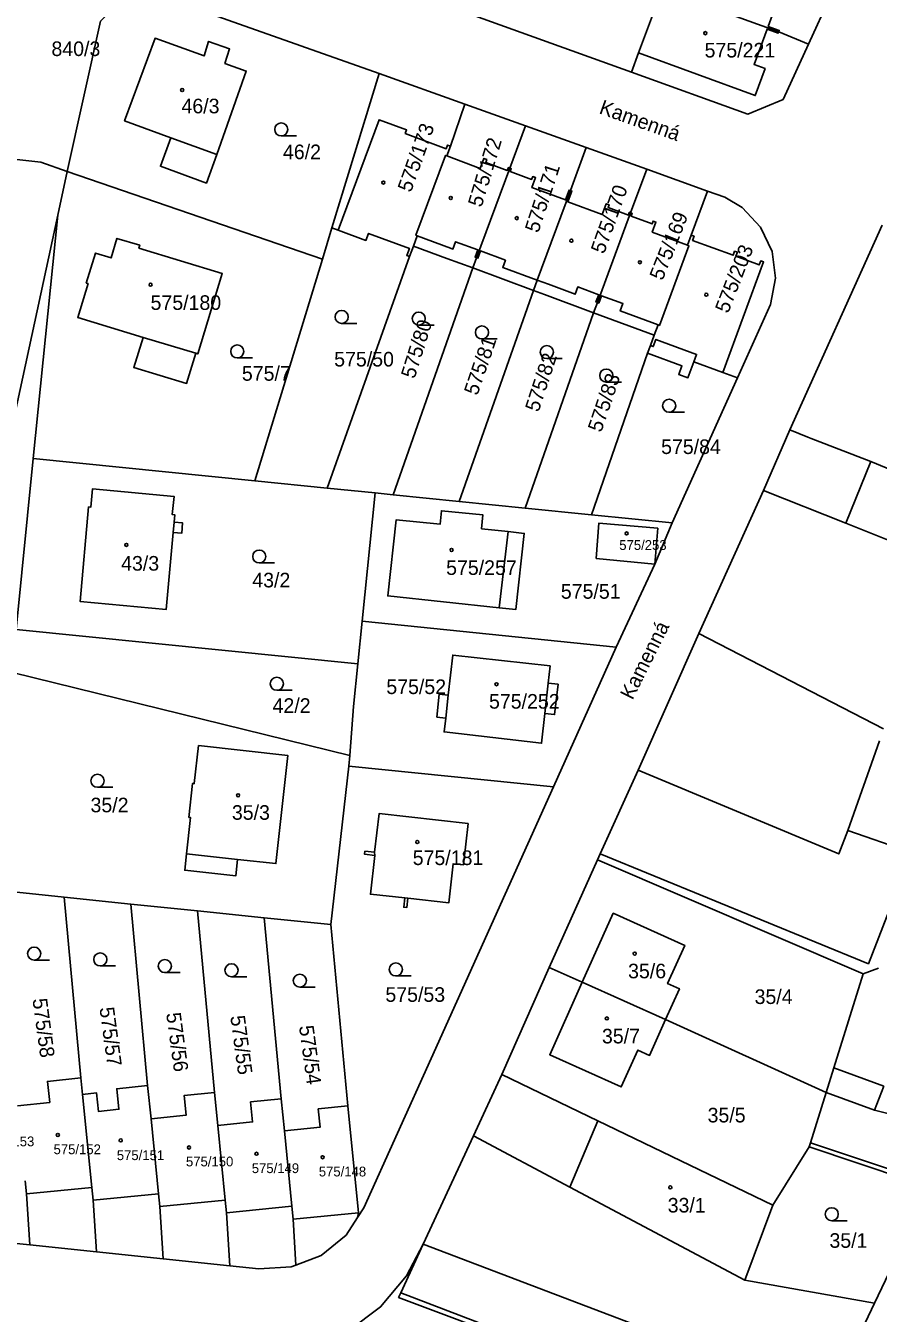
# Model space of a CAD drawing. Extents: x -737240 to -735272, y -1119606 to -1117878.
# Drawn here: x -737081.3 to -736982.1, y -1119014.9 to -1118864.9 of the extents above; entities that cross this region are included whole.
import ezdxf

# ---------------------------------------------------------------- set-up
doc = ezdxf.new("R2010")
doc.units = 0
for name, color, linetype in [('Level 1', 7, 'Continuous'), ('Level 15', 7, 'Continuous'), ('Level 16', 7, 'Continuous'), ('Level 18', 7, 'Continuous'), ('Level 19', 7, 'Continuous'), ('Level 25', 7, 'Continuous'), ('Level 4', 7, 'Continuous')]:
    doc.layers.add(name, color=color, linetype=linetype)

msp = doc.modelspace()

# ---------------------------------------------------------------- linework, layer by layer
at = {"layer": 'Level 1'}
for p, q in [((-737007.25, -1118860.74), (-737009.97, -1118868.1)), ((-736993.66, -1118865.64), (-737007.25, -1118860.74)), ((-736990.21, -1118867.1), (-736987.06, -1118860.23)), ((-737076.46, -1118881.9), (-737072.59, -1118864.42)), ((-737030.53, -1118863.26), (-737010.8, -1118870.36)), ((-736990.21, -1118867.1), (-736993.66, -1118865.64)), ((-737009.97, -1118868.1), (-737010.8, -1118870.36)), ((-737040.17, -1118870.49), (-737045.66, -1118888.46)), ((-737030.19, -1118874.06), (-737040.17, -1118870.49)), ((-737031.87, -1118878.96), (-737030.19, -1118874.06)), ((-737023.12, -1118876.59), (-737030.19, -1118874.06)), ((-737024.97, -1118881.51), (-737023.12, -1118876.59)), ((-737016.06, -1118879.12), (-737023.12, -1118876.59)), ((-737032.29, -1118880.11), (-737031.87, -1118878.96)), ((-737017.9, -1118884.13), (-737016.06, -1118879.12)), ((-737009, -1118881.66), (-737016.06, -1118879.12)), ((-737077.57, -1118886.99), (-737076.46, -1118881.9)), ((-737046.77, -1118892.11), (-737076.46, -1118881.9)), ((-737028.84, -1118891.96), (-737024.97, -1118881.51)), ((-737010.9, -1118886.72), (-737009, -1118881.66)), ((-737001.94, -1118884.19), (-737009, -1118881.66)), ((-737021.77, -1118894.57), (-737017.9, -1118884.13)), ((-737001.94, -1118884.19), (-737003.84, -1118889.33)), ((-737077.57, -1118886.99), (-737092.86, -1118957.66)), ((-737080.43, -1118915.33), (-737077.57, -1118886.99)), ((-737014.77, -1118897.17), (-737010.9, -1118886.72)), ((-737045.66, -1118888.46), (-737046.77, -1118892.11)), ((-737045.66, -1118888.46), (-737044.94, -1118888.73)), ((-736992.35, -1118912.01), (-736981.62, -1118888.15)), ((-737036.18, -1118890.6), (-737035.73, -1118889.4)), ((-737003.84, -1118889.33), (-737004.27, -1118890.5)), ((-737036.62, -1118891.81), (-737036.18, -1118890.6)), ((-737046.77, -1118892.11), (-737054.65, -1118917.93)), ((-737036.62, -1118891.81), (-737046.23, -1118918.78)), ((-737038.54, -1118919.56), (-737029.28, -1118893.15)), ((-737029.28, -1118893.15), (-737028.84, -1118891.96)), ((-737029.28, -1118893.15), (-737022.21, -1118895.77)), ((-737022.21, -1118895.77), (-737021.77, -1118894.57)), ((-737030.85, -1118920.33), (-737022.21, -1118895.77)), ((-737015.21, -1118898.36), (-737014.77, -1118897.17)), ((-737015.21, -1118898.36), (-737023.16, -1118921.11)), ((-737015.21, -1118898.36), (-737008.15, -1118900.97)), ((-737007.7, -1118899.78), (-737008.15, -1118900.97)), ((-737008.59, -1118902.18), (-737008.92, -1118903.06)), ((-737008.15, -1118900.97), (-737008.59, -1118902.18)), ((-737008.92, -1118903.06), (-737015.45, -1118921.89)), ((-737003.53, -1118904.06), (-737000.18, -1118905.3)), ((-737006.06, -1118922.84), (-736998.45, -1118905.94)), ((-737000.18, -1118905.3), (-736998.45, -1118905.94)), ((-736995.45, -1118919.05), (-736992.35, -1118912.01)), ((-737082.43, -1118935.23), (-737080.43, -1118915.33)), ((-737080.43, -1118915.33), (-737054.65, -1118917.93)), ((-737054.65, -1118917.93), (-737046.23, -1118918.78)), ((-737046.23, -1118918.78), (-737040.63, -1118919.35)), ((-737040.63, -1118919.35), (-737042.16, -1118934.27)), ((-737040.63, -1118919.35), (-737038.54, -1118919.56)), ((-737030.85, -1118920.33), (-737038.54, -1118919.56)), ((-737002.97, -1118935.72), (-736995.45, -1118919.05)), ((-737023.16, -1118921.11), (-737030.85, -1118920.33)), ((-737015.45, -1118921.89), (-737023.16, -1118921.11)), ((-737015.45, -1118921.89), (-737006.06, -1118922.84)), ((-737008.07, -1118927.62), (-737006.06, -1118922.84)), ((-737012.57, -1118937.31), (-737008.07, -1118927.62)), ((-737042.16, -1118934.27), (-737042.64, -1118939.25)), ((-737012.57, -1118937.31), (-737042.16, -1118934.27)), ((-737082.43, -1118935.23), (-737042.64, -1118939.25)), ((-737010.03, -1118951.63), (-737002.97, -1118935.72)), ((-736981.48, -1118946.83), (-737002.97, -1118935.72)), ((-737019.89, -1118953.57), (-737012.57, -1118937.31)), ((-737043.57, -1118949.91), (-737082.82, -1118940.25)), ((-737043.57, -1118949.91), (-737043.71, -1118951.15)), ((-737043.71, -1118951.15), (-737045.79, -1118969.61)), ((-737019.89, -1118953.57), (-737043.71, -1118951.15)), ((-737014.45, -1118961.37), (-737010.03, -1118951.63)), ((-737020.36, -1118974.59), (-737014.76, -1118962.06)), ((-737014.76, -1118962.06), (-737014.45, -1118961.37)), ((-737014.76, -1118962.06), (-736983.85, -1118975.35)), ((-737076.82, -1118966.41), (-737084.58, -1118965.6)), ((-737074.89, -1118987.46), (-737076.82, -1118966.41)), ((-737069.07, -1118967.21), (-737076.82, -1118966.41)), ((-737067.11, -1118988.35), (-737069.07, -1118967.21)), ((-737061.3, -1118968.01), (-737069.07, -1118967.21)), ((-737053.55, -1118968.81), (-737061.3, -1118968.01)), ((-737059.34, -1118989.15), (-737061.3, -1118968.01)), ((-737045.79, -1118969.61), (-737053.55, -1118968.81)), ((-737051.57, -1118989.89), (-737053.55, -1118968.81)), ((-737043.8, -1118990.72), (-737045.79, -1118969.61)), ((-737025.89, -1118987.06), (-737020.36, -1118974.59)), ((-737016.53, -1118976.3), (-737020.36, -1118974.59)), ((-736983.85, -1118975.35), (-736987.26, -1118986.29)), ((-736983.85, -1118975.35), (-736982.04, -1118974.66)), ((-737006.82, -1118980.64), (-737016.53, -1118976.3)), ((-736988.15, -1118989.15), (-737006.82, -1118980.64)), ((-737074.69, -1118989.38), (-737074.89, -1118987.46)), ((-737029.19, -1118994.2), (-737025.89, -1118987.06)), ((-737025.89, -1118987.06), (-737014.71, -1118992.46)), ((-736987.26, -1118986.29), (-736988.15, -1118989.15)), ((-737066.71, -1118992.22), (-737067.11, -1118988.35)), ((-737073.61, -1119000.2), (-737074.69, -1118989.38)), ((-737058.94, -1118992.98), (-737059.34, -1118989.15)), ((-737051.19, -1118993.62), (-737051.57, -1118989.89)), ((-736988.15, -1118989.15), (-736989.98, -1118995.02)), ((-737042.56, -1119003.16), (-737043.8, -1118990.72)), ((-737065.85, -1119000.94), (-737066.71, -1118992.22)), ((-737058.08, -1119001.68), (-737058.94, -1118992.98)), ((-737050.32, -1119002.41), (-737051.19, -1118993.62)), ((-737014.71, -1118992.46), (-736994.36, -1119002.27)), ((-737035.04, -1119006.83), (-737029.19, -1118994.2)), ((-736989.98, -1118995.02), (-736990.13, -1118995.5)), ((-736994.36, -1119002.27), (-736990.13, -1118995.5)), ((-736990.13, -1118995.5), (-736976.1, -1119000.18)), ((-737081.22, -1119000.96), (-737081.37, -1118999.45)), ((-737080.82, -1119006.91), (-737081.22, -1119000.96)), ((-737073.46, -1119001.7), (-737073.61, -1119000.2)), ((-737065.7, -1119002.44), (-737065.85, -1119000.94)), ((-736976.1, -1119000.18), (-736982.52, -1119013.7)), ((-737073.06, -1119007.71), (-737073.46, -1119001.7)), ((-737065.3, -1119008.52), (-737065.7, -1119002.44)), ((-737057.94, -1119003.17), (-737058.08, -1119001.68)), ((-737050.17, -1119003.92), (-737050.32, -1119002.41)), ((-736994.36, -1119002.27), (-736997.61, -1119011.01)), ((-737057.54, -1119009.32), (-737057.94, -1119003.17)), ((-737049.85, -1119009.25), (-737050.17, -1119003.92)), ((-737042.68, -1119003.73), (-737042.56, -1119003.16)), ((-737088.58, -1119006.11), (-737080.82, -1119006.91)), ((-737080.82, -1119006.91), (-737073.06, -1119007.71)), ((-737035.04, -1119006.83), (-737037.65, -1119012.49)), ((-737073.06, -1119007.71), (-737065.3, -1119008.52)), ((-737065.3, -1119008.52), (-737057.54, -1119009.32)), ((-736997.61, -1119011.01), (-736982.52, -1119013.7)), ((-736982.52, -1119013.7), (-736990.96, -1119031.47))]:
    msp.add_line(p, q, dxfattribs=at)
for points in [[(-737072.59, -1118864.42), (-737070.24, -1118862.01), (-737066.84, -1118861.04), (-737040.17, -1118870.49)], [(-737059.06, -1118879.93), (-737055.63, -1118870.23), (-737058.12, -1118869.33), (-737057.57, -1118867.65), (-737060.02, -1118866.77), (-737060.52, -1118868.46), (-737066.25, -1118866.39), (-737069.79, -1118876.03), (-737064.41, -1118877.99)], [(-737010.8, -1118870.36), (-736997.24, -1118875.23), (-736993.16, -1118873.52), (-736990.21, -1118867.1)], [(-737064.41, -1118877.99), (-737065.62, -1118881.31), (-737060.27, -1118883.26), (-737059.06, -1118879.93)], [(-737085.87, -1118880.12), (-737079.53, -1118880.81), (-737076.46, -1118881.9)], [(-737035.73, -1118889.4), (-737035.89, -1118889.34), (-737032.45, -1118880.05), (-737032.29, -1118880.11)], [(-736998.45, -1118905.94), (-736994.6, -1118897.4), (-736994.03, -1118894.32), (-736994.43, -1118891.22), (-736995.77, -1118888.39), (-736997.92, -1118886.12), (-736999.92, -1118884.92), (-737001.94, -1118884.19)], [(-737061.51, -1118903.08), (-737061.27, -1118903.16), (-737058.42, -1118893.81), (-737068.12, -1118890.84), (-737068.02, -1118890.51), (-737070.68, -1118889.7), (-737071.37, -1118891.97), (-737073.18, -1118891.42), (-737074.25, -1118894.9), (-737074.04, -1118894.97), (-737075.24, -1118898.91), (-737067.65, -1118901.23)], [(-737044.94, -1118888.73), (-737041.7, -1118889.93), (-737041.4, -1118889.12), (-737036.65, -1118890.88), (-737036.95, -1118891.69), (-737036.62, -1118891.81)], [(-737036.18, -1118890.6), (-737032.3, -1118892.03), (-737029.28, -1118893.15)], [(-737004.27, -1118890.5), (-737004.11, -1118890.56), (-737007.54, -1118899.84), (-737007.7, -1118899.78)], [(-737022.21, -1118895.77), (-737020.91, -1118896.25), (-737015.21, -1118898.36)], [(-737067.65, -1118901.23), (-737068.72, -1118904.72), (-737062.58, -1118906.6), (-737061.51, -1118903.08)], [(-737008.92, -1118903.06), (-737004.92, -1118904.54), (-737005.3, -1118905.54), (-737004.23, -1118905.94), (-737003.53, -1118904.06)], [(-736992.35, -1118912.01), (-736990.26, -1118912.86), (-736989.88, -1118913.01), (-736982.95, -1118915.69)], [(-736982.95, -1118915.69), (-736981.14, -1118916.42), (-736979.8, -1118917.02)], [(-737064.01, -1118922.74), (-737063.93, -1118921.9), (-737064.24, -1118921.87), (-737064.04, -1118919.75), (-737073.53, -1118918.88), (-737073.73, -1118921), (-737073.98, -1118920.98), (-737074.96, -1118931.99), (-737064.95, -1118932.91), (-737064.12, -1118923.94)], [(-737025.15, -1118923.85), (-737028.25, -1118923.51), (-737028.09, -1118921.91), (-737032.92, -1118921.42), (-737033.08, -1118922.99), (-737038.2, -1118922.48), (-737039.17, -1118931.34), (-737026.19, -1118932.73)], [(-737064.12, -1118923.94), (-737063.15, -1118924.03), (-737063.04, -1118922.83), (-737064.01, -1118922.74)], [(-737008.07, -1118927.62), (-737007.75, -1118923.46), (-737014.59, -1118922.86), (-737014.9, -1118926.97), (-737008.07, -1118927.62)], [(-737026.19, -1118932.73), (-737024.27, -1118932.93), (-737023.28, -1118924.06), (-737025.15, -1118923.85)], [(-737042.64, -1118939.25), (-737043.14, -1118944.22), (-737043.57, -1118949.91)], [(-737020.5, -1118941.48), (-737020.28, -1118939.49), (-737031.6, -1118938.23), (-737032.12, -1118942.89)], [(-737020.89, -1118945.02), (-737019.74, -1118945.15), (-737019.34, -1118941.61), (-737020.5, -1118941.48)], [(-737032.12, -1118942.89), (-737033.17, -1118942.77), (-737033.45, -1118945.45), (-737032.42, -1118945.57)], [(-737032.42, -1118945.57), (-737032.6, -1118947.17), (-737021.27, -1118948.48), (-737020.89, -1118945.02)], [(-737056.64, -1118962.01), (-737052.18, -1118962.5), (-737050.79, -1118949.92), (-737061.19, -1118948.77), (-737061.68, -1118953.18), (-737061.88, -1118953.16), (-737062.31, -1118957.12), (-737062.12, -1118957.14), (-737062.58, -1118961.35)], [(-737042.68, -1119003.73), (-737041.95, -1119002.6), (-737034.13, -1118985.19), (-737019.89, -1118953.57)], [(-737036.83, -1118966.54), (-737032.06, -1118967.08), (-737031.55, -1118962.53), (-737030.35, -1118962.66), (-737029.81, -1118957.84), (-737040.18, -1118956.67), (-737040.69, -1118961.19)], [(-737062.58, -1118961.35), (-737062.79, -1118963.28), (-737056.85, -1118963.94), (-737056.64, -1118962.01)], [(-737040.69, -1118961.19), (-737041.82, -1118961.07), (-737041.86, -1118961.41), (-737040.67, -1118961.55)], [(-737040.67, -1118961.55), (-737041.18, -1118966.07), (-737037.18, -1118966.5)], [(-737037.18, -1118966.5), (-737037.3, -1118967.59), (-737036.95, -1118967.63), (-737036.83, -1118966.54)], [(-737006.82, -1118980.64), (-737005.22, -1118977.08), (-737006.59, -1118976.47), (-737004.59, -1118972.03), (-737012.93, -1118968.29), (-737016.53, -1118976.3)], [(-737016.53, -1118976.3), (-737020.32, -1118984.76), (-737011.99, -1118988.5), (-737010.06, -1118984.21), (-737008.7, -1118984.83), (-737006.82, -1118980.64)], [(-737074.89, -1118987.46), (-737078.77, -1118987.86), (-737078.51, -1118990.32), (-737082.25, -1118990.71)], [(-737067.11, -1118988.35), (-737070.7, -1118988.71), (-737070.46, -1118991.1), (-737072.84, -1118991.35), (-737073.06, -1118989.21), (-737074.69, -1118989.38)], [(-737059.34, -1118989.15), (-737062.87, -1118989.52), (-737062.63, -1118991.8), (-737066.71, -1118992.22)], [(-737051.57, -1118989.89), (-737055.12, -1118990.26), (-737054.89, -1118992.58), (-737058.94, -1118992.98)], [(-737043.8, -1118990.72), (-737047.25, -1118991.07), (-737047.03, -1118993.19), (-737051.19, -1118993.62)], [(-737049.85, -1119009.25), (-737046.91, -1119008.12), (-737043.99, -1119005.75), (-737042.68, -1119003.73)], [(-737049.67, -1119019.08), (-737048.08, -1119018.81), (-737043.76, -1119016.95), (-737040, -1119014.13), (-737037, -1119010.51), (-737035.04, -1119006.83)], [(-737057.54, -1119009.32), (-737054.16, -1119009.67), (-737050.41, -1119009.47), (-737049.85, -1119009.25)], [(-737037.65, -1119012.49), (-737037.9, -1119013.02), (-737023.43, -1119018.46)]]:
    msp.add_lwpolyline(points, dxfattribs=at)
at = {"layer": 'Level 25'}
for p, q in [((-737049.778, -1118877.77), (-737051.56, -1118877.77)), ((-737042.748, -1118899.6), (-737044.53, -1118899.6)), ((-737033.778, -1118899.8), (-737035.56, -1118899.8)), ((-737026.418, -1118901.41), (-737028.2, -1118901.41)), ((-737054.898, -1118903.62), (-737056.68, -1118903.62)), ((-737018.868, -1118903.7), (-737020.65, -1118903.7)), ((-737011.948, -1118906.43), (-737013.73, -1118906.43)), ((-737004.638, -1118909.94), (-737006.42, -1118909.94)), ((-737052.338, -1118927.5), (-737054.12, -1118927.5)), ((-737050.288, -1118942.32), (-737052.07, -1118942.32)), ((-737071.158, -1118953.62), (-737072.94, -1118953.62)), ((-737078.538, -1118973.74), (-737080.32, -1118973.74)), ((-737070.838, -1118974.42), (-737072.62, -1118974.42)), ((-737063.328, -1118975.19), (-737065.11, -1118975.19)), ((-737036.448, -1118975.58), (-737038.23, -1118975.58)), ((-737055.568, -1118975.68), (-737057.35, -1118975.68)), ((-737047.618, -1118976.89), (-737049.4, -1118976.89)), ((-736985.708, -1119004.08), (-736987.49, -1119004.08))]:
    msp.add_line(p, q, dxfattribs=at)
for centre, major_axis, ratio in [((-737002.2, -1118865.81), (0.18, 0), 0.9848078), ((-737063.09, -1118872.43), (0.18, 0), 0.9848078), ((-737051.56, -1118877.014), (0.764, 0), 0.9894236), ((-737039.67, -1118883.2), (0.18, 0), 0.9848078), ((-737031.83, -1118885), (0.18, 0), 0.9848078), ((-737024.15, -1118887.35), (0.18, 0), 0.9848078), ((-737017.79, -1118889.97), (0.18, 0), 0.9848078), ((-737009.82, -1118892.48), (0.18, 0), 0.9848078), ((-737066.77, -1118895.1), (0.18, 0), 0.9848078), ((-737002.09, -1118896.26), (0.18, 0), 0.9848078), ((-737044.53, -1118898.844), (0.764, 0), 0.9894236), ((-737035.56, -1118899.044), (0.764, 0), 0.9894236), ((-737028.2, -1118900.654), (0.764, 0), 0.9894236), ((-737056.68, -1118902.864), (0.764, 0), 0.9894236), ((-737020.65, -1118902.944), (0.764, 0), 0.9894236), ((-737013.73, -1118905.674), (0.764, 0), 0.9894236), ((-737006.42, -1118909.184), (0.764, 0), 0.9894236), ((-737011.36, -1118924.06), (0.18, 0), 0.9848078), ((-737069.58, -1118925.39), (0.18, 0), 0.9848078), ((-737054.12, -1118926.744), (0.764, 0), 0.9894236), ((-737031.74, -1118925.98), (0.18, 0), 0.9848078), ((-737052.07, -1118941.564), (0.764, 0), 0.9894236), ((-737026.51, -1118941.62), (0.18, 0), 0.9848078), ((-737072.94, -1118952.864), (0.764, 0), 0.9894236), ((-737056.58, -1118954.55), (0.18, 0), 0.9848078), ((-737035.73, -1118959.99), (0.18, 0), 0.9848078), ((-737080.32, -1118972.984), (0.764, 0), 0.9894236), ((-737072.62, -1118973.664), (0.764, 0), 0.9894236), ((-737065.11, -1118974.434), (0.764, 0), 0.9894236), ((-737038.23, -1118974.824), (0.764, 0), 0.9894236), ((-737010.42, -1118972.99), (0.18, 0), 0.9848078), ((-737057.35, -1118974.924), (0.764, 0), 0.9894236), ((-737049.4, -1118976.134), (0.764, 0), 0.9894236), ((-737013.67, -1118980.53), (0.18, 0), 0.9848078), ((-737077.56, -1118994.1), (0.18, 0), 0.9848078), ((-737070.24, -1118994.73), (0.18, 0), 0.9848078), ((-737062.29, -1118995.56), (0.18, 0), 0.9848078), ((-737054.44, -1118996.29), (0.18, 0), 0.9848078), ((-737046.74, -1118996.69), (0.18, 0), 0.9848078), ((-737006.28, -1119000.2), (0.18, 0), 0.9848078), ((-736987.49, -1119003.324), (0.764, 0), 0.9894236)]:
    msp.add_ellipse(centre, major_axis=major_axis, ratio=ratio, dxfattribs=at)
at = {"layer": 'Level 4'}
for p, q in [((-737059.06, -1118879.93), (-737064.41, -1118877.99)), ((-737067.65, -1118901.23), (-737061.51, -1118903.08)), ((-736985.86, -1118922.86), (-736982.95, -1118915.69)), ((-736995.45, -1118919.05), (-736985.86, -1118922.86)), ((-737064.01, -1118922.74), (-737064.12, -1118923.94)), ((-736985.86, -1118922.86), (-736974.54, -1118927.38)), ((-737025.15, -1118923.85), (-737026.19, -1118932.73)), ((-737020.89, -1118945.02), (-737020.5, -1118941.48)), ((-737032.12, -1118942.89), (-737032.42, -1118945.57)), ((-736985.61, -1118958.63), (-736981.92, -1118948.21)), ((-736978.21, -1118961.23), (-736985.61, -1118958.63)), ((-737056.64, -1118962.01), (-737062.58, -1118961.35)), ((-737040.69, -1118961.19), (-737040.67, -1118961.55)), ((-737036.83, -1118966.54), (-737037.18, -1118966.5)), ((-736987.26, -1118986.29), (-736981.42, -1118988.42)), ((-736981.42, -1118988.42), (-736982.52, -1118991.21)), ((-736988.15, -1118989.15), (-736982.52, -1118991.21)), ((-736982.52, -1118991.21), (-736976.65, -1118992.71)), ((-737014.71, -1118992.46), (-737017.96, -1119000.18)), ((-737017.96, -1119000.18), (-737029.19, -1118994.2)), ((-736975.83, -1118999.73), (-736989.98, -1118995.02)), ((-737073.61, -1119000.2), (-737081.22, -1119000.96)), ((-737065.85, -1119000.94), (-737073.46, -1119001.7)), ((-736997.61, -1119011.01), (-737017.96, -1119000.18)), ((-737058.08, -1119001.68), (-737065.7, -1119002.44)), ((-737050.32, -1119002.41), (-737057.94, -1119003.17)), ((-737050.17, -1119003.92), (-737042.56, -1119003.16))]:
    msp.add_line(p, q, dxfattribs=at)
for points in [[(-736991.13, -1118858.74), (-736992.19, -1118861.63), (-736993.48, -1118861.16), (-736994.89, -1118865.02), (-736993.61, -1118865.49), (-736993.66, -1118865.64)], [(-736993.66, -1118865.64), (-736993.72, -1118865.8), (-736995.01, -1118865.33), (-736996.53, -1118869.47), (-736995.24, -1118869.94), (-736996.39, -1118873.08), (-737009.97, -1118868.1)], [(-737031.87, -1118878.96), (-737032.2, -1118878.84), (-737032.35, -1118879.26), (-737037.13, -1118877.49), (-737036.98, -1118877.07), (-737040.18, -1118875.88), (-737044.94, -1118888.73)], [(-737032.29, -1118880.11), (-737028.4, -1118881.56), (-737027.97, -1118880.4), (-737027.64, -1118880.52), (-737027.76, -1118880.85), (-737025.25, -1118881.78), (-737025.13, -1118881.45), (-737024.97, -1118881.51)], [(-737024.97, -1118881.51), (-737024.8, -1118881.57), (-737024.93, -1118881.9), (-737022.42, -1118882.83), (-737022.29, -1118882.5), (-737021.96, -1118882.63), (-737022.38, -1118883.78), (-737018.49, -1118885.23), (-737018.06, -1118884.07), (-737017.9, -1118884.13)], [(-737017.9, -1118884.13), (-737017.73, -1118884.19), (-737018.2, -1118885.46), (-737014.21, -1118886.94), (-737013.74, -1118885.67), (-737013.41, -1118885.79), (-737013.53, -1118886.12), (-737011.13, -1118887.01), (-737011.06, -1118886.66), (-737010.9, -1118886.72)], [(-737010.9, -1118886.72), (-737010.73, -1118886.78), (-737010.85, -1118887.11), (-737008.41, -1118888.02), (-737008.29, -1118887.69), (-737007.96, -1118887.81), (-737008.39, -1118888.97), (-737004.27, -1118890.5)], [(-737035.73, -1118889.4), (-737031.86, -1118890.84), (-737031.58, -1118890.94), (-737031.27, -1118890.09), (-737028.68, -1118891.05), (-737029, -1118891.9), (-737028.84, -1118891.96)], [(-737003.84, -1118889.33), (-737003.51, -1118889.46), (-737003.68, -1118889.93), (-736998.98, -1118891.67), (-736998.8, -1118891.2), (-736998.47, -1118891.32), (-736998.65, -1118891.79), (-736995.92, -1118892.8), (-736995.75, -1118892.33), (-736995.42, -1118892.45), (-737000.18, -1118905.3)], [(-737028.84, -1118891.96), (-737028.67, -1118892.02), (-737028.36, -1118891.17), (-737025.47, -1118892.24), (-737025.79, -1118893.09), (-737021.77, -1118894.57)], [(-737014.77, -1118897.17), (-737014.93, -1118897.11), (-737014.61, -1118896.26), (-737017.06, -1118895.36), (-737017.37, -1118896.2), (-737020.47, -1118895.05), (-737021.77, -1118894.57)], [(-737014.77, -1118897.17), (-737014.6, -1118897.23), (-737014.29, -1118896.38), (-737011.8, -1118897.3), (-737012.11, -1118898.15), (-737007.7, -1118899.78)], [(-737003.53, -1118904.06), (-737003.22, -1118903.21), (-737007.95, -1118901.46), (-737008.26, -1118902.31), (-737008.59, -1118902.18)], [(-737010.03, -1118951.63), (-736986.67, -1118961.38), (-736985.61, -1118958.63)], [(-737014.45, -1118961.37), (-736983.22, -1118974.17), (-736978.21, -1118961.23)], [(-737037.65, -1119012.49), (-737002.69, -1119025.87), (-737000.69, -1119019.91), (-737035.04, -1119006.83)]]:
    msp.add_lwpolyline(points, dxfattribs=at)

# ---------------------------------------------------------------- texts
at = {"layer": 'Level 15'}
for rotation, p in [(340.34184, (-737014.67, -1118875.12)), (63.43758, (-737010.69, -1118943.54))]:
    msp.add_text('Kamenná', height=1.7, rotation=rotation, dxfattribs=at).set_placement(p)
at = {"layer": 'Level 16'}
msp.add_text('840/3', height=1.7, dxfattribs=at).set_placement((-737078.305, -1118868.47))
at = {"layer": 'Level 18'}
for s, p in [('46/2', (-737051.36, -1118880.48)), ('575/50', (-737045.4, -1118904.62)), ('575/7', (-737056.14, -1118906.28)), ('575/84', (-737007.35, -1118914.81)), ('43/2', (-737054.93, -1118930.34)), ('575/51', (-737019.02, -1118931.66)), ('575/52', (-737039.33, -1118942.76)), ('42/2', (-737052.57, -1118944.95)), ('35/2', (-737073.76, -1118956.53)), ('575/53', (-737039.44, -1118978.6)), ('35/4', (-736996.47, -1118978.85)), ('35/5', (-737001.94, -1118992.64)), ('35/1', (-736987.76, -1119007.24))]:
    msp.add_text(s, height=1.7, dxfattribs=at).set_placement(p)
for s, rotation, p in [('575/80', 72.63477, (-737036.05, -1118906.13)), ('575/81', 71.00883, (-737028.74, -1118908.08)), ('575/82', 71.72073, (-737021.62, -1118910.01)), ('575/83', 71.19927, (-737014.32, -1118912.37)), ('575/58', 277.70373, (-737080.518, -1118978.297)), ('575/57', 277.70373, (-737072.718, -1118979.317)), ('575/56', 277.70373, (-737064.958, -1118979.947)), ('575/55', 277.70373, (-737057.498, -1118980.287)), ('575/54', 277.70373, (-737049.498, -1118981.447))]:
    msp.add_text(s, height=1.7, rotation=rotation, dxfattribs=at).set_placement(p)
at = {"layer": 'Level 19'}
for s, height, p in [('575/221', 1.7, (-737002.29, -1118868.64)), ('46/3', 1.7, (-737063.17, -1118875.14)), ('575/180', 1.7, (-737066.77, -1118898.03)), ('575/253', 1.14, (-737012.22, -1118925.98)), ('43/3', 1.7, (-737070.195, -1118928.39)), ('575/257', 1.7, (-737032.37, -1118928.89)), ('575/252', 1.7, (-737027.38, -1118944.46)), ('35/3', 1.7, (-737057.305, -1118957.4)), ('575/181', 1.7, (-737036.26, -1118962.67)), ('35/6', 1.7, (-737011.195, -1118975.86)), ('35/7', 1.7, (-737014.235, -1118983.44)), ('575/153', 1.14, (-737085.81, -1118995.42)), ('575/152', 1.14, (-737078.06, -1118996.34)), ('575/151', 1.14, (-737070.7, -1118997.03)), ('575/150', 1.14, (-737062.65, -1118997.76)), ('575/149', 1.14, (-737054.99, -1118998.54)), ('575/148', 1.14, (-737047.19, -1118998.93)), ('33/1', 1.7, (-737006.585, -1119003.13))]:
    msp.add_text(s, height=height, dxfattribs=at).set_placement(p)
for s, rotation, p in [('575/173', 70.32915, (-737036.47, -1118884.43)), ('575/172', 73.10223, (-737028.25, -1118886.16)), ('575/171', 71.84475, (-737021.64, -1118889.15)), ('575/170', 70.19253, (-737013.99, -1118891.6)), ('575/169', 68.42124, (-737007.19, -1118894.7)), ('575/203', 68.7204, (-736999.55, -1118898.52))]:
    msp.add_text(s, height=1.7, rotation=rotation, dxfattribs=at).set_placement(p)

doc.saveas('drawing.dxf')
